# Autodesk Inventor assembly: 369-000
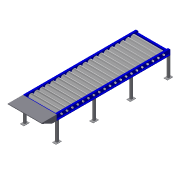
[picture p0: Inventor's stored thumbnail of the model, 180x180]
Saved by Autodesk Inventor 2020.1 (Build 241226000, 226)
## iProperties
Manager: www.cadconsulting.pl
Company: Fabian Stasiak CAD Consulting
Created: 2005-09
Part Number: 369-000
Document SubType Name: Assembly
Designer: F.Stasiak
Project: Przenośnik XC850
Description: Przenośnik rolkowy XC850
Authority: B.S.
Title: Przenośnik rolkowy
Subject: Zbiór ćwiczeń. Autodesk Inventor 2020. Kurs podstawowy
Author: F.Stasiak
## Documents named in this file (11)
- C:\2020_Kurs_podstawowy\R9 Zarządzanie plikami\369-000.iam
- C:\2020_Kurs_podstawowy\R9 Zarządzanie plikami\Bok_prawy.ipt
- C:\2020_Kurs_podstawowy\R9 Zarządzanie plikami\Poprzeczka.ipt
- C:\2020_Kurs_podstawowy\R9 Zarządzanie plikami\123-004.ipt
- C:\2020_Kurs_podstawowy\R9 Zarządzanie plikami\Rolka.ipt
- C:\2020_Kurs_podstawowy\R9 Zarządzanie plikami\Bok_lewy.ipt
- C:\2020_Kurs_podstawowy\R9 Zarządzanie plikami\475-001.ipt
- C:\2020_Kurs_podstawowy\R9 Zarządzanie plikami\369-000\Design Accelerator\Połączenie gwintowe5.iam
- C:\2020_Kurs_podstawowy\R9 Zarządzanie plikami\369-000\Design Accelerator\Połączenie gwintowe6.iam
- C:\2020_Kurs_podstawowy\R9 Zarządzanie plikami\369-000\Design Accelerator\Połączenie gwintowe7.iam
- C:\2020_Kurs_podstawowy\R9 Zarządzanie plikami\369-000\Design Accelerator\Połączenie gwintowe9.iam
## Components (37 placed, 7 different names)
1. Bok_prawy:1 — Zestawiający:2, Równoległy:8, Równoległy:9, Zestawiający:4, Wstaw:2, Równoległy:10, Równoległy:11, Zestawiający:5, Równoległy:12, Równoległy:13, Zestawiający:7, Równoległy:14, Równoległy:15
2. Bok_lewy:1 — Równoległy:10, Równoległy:11, Zestawiający:5, Wstaw:3, Zestawiający:6, Równoległy:16
3. Poprzeczka:1 — Zestawiający:2, Zestawiający:6
4. Poprzeczka:2 — Równoległy:12, Równoległy:13
5. 475-001:1 — Zestawiający:7, Równoległy:14, Równoległy:15, Równoległy:16, Zestawiający:8, Zestawiający:9, Zestawiający:10, Zestawiający:11, Zestawiający:12, Zestawiający:13, Zestawiający:14, Zestawiający:15
6. Połączenie gwintowe:1 [sub-assembly] — Zestawiający:8, Zestawiający:9
7. Połączenie gwintowe:2 [sub-assembly] — Zestawiający:10, Zestawiający:11
8. Połączenie gwintowe:3 [sub-assembly] — Zestawiający:12, Zestawiający:13
9. Połączenie gwintowe:4 [sub-assembly] — Zestawiający:14, Zestawiający:15
10. 123-004:1 — Równoległy:8, Równoległy:9, Zestawiający:4
11. 123-004:2
12. 123-004:3
13. 123-004:4
14. 123-004:5
15. 123-004:6
16. 123-004:7
17. 123-004:8
18. Rolka:1 — Wstaw:2, Wstaw:3
19. Rolka:2
20. Rolka:3
21. Rolka:4
22. Rolka:5
23. Rolka:6
24. Rolka:7
25. Rolka:8
26. Rolka:9
27. Rolka:10
28. Rolka:11
29. Rolka:12
30. Rolka:13
31. Rolka:14
32. Rolka:15
33. Rolka:16
34. Rolka:17
35. Rolka:18
36. Rolka:19
37. Rolka:20
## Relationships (24: Mate 13, Flush 9, Insert 2)
- Zestawiający:2 [Mate]: Bok_prawy:1 ↔ Poprzeczka:1
- Równoległy:8 [Flush]: Bok_prawy:1 ↔ 123-004:1
- Równoległy:9 [Flush]: Bok_prawy:1 ↔ 123-004:1
- Zestawiający:4 [Mate]: Bok_prawy:1 ↔ 123-004:1
- Wstaw:2 [Insert]: Bok_prawy:1 ↔ Rolka:1
- Równoległy:10 [Flush]: Bok_prawy:1 ↔ Bok_lewy:1
- Równoległy:11 [Flush]: Bok_prawy:1 ↔ Bok_lewy:1
- Zestawiający:5 [Mate]: Bok_prawy:1 ↔ Bok_lewy:1
- Wstaw:3 [Insert]: Bok_lewy:1 ↔ Rolka:1
- Zestawiający:6 [Mate]: Bok_lewy:1 ↔ Poprzeczka:1
- Równoległy:12 [Flush]: Bok_prawy:1 ↔ Poprzeczka:2
- Równoległy:13 [Flush]: Bok_prawy:1 ↔ Poprzeczka:2
- Zestawiający:7 [Mate]: Bok_prawy:1 ↔ 475-001:1
- Równoległy:14 [Flush]: Bok_prawy:1 ↔ 475-001:1
- Równoległy:15 [Flush]: Bok_prawy:1 ↔ 475-001:1
- Równoległy:16 [Flush]: Bok_lewy:1 ↔ 475-001:1
- Zestawiający:8 [Mate]: 475-001:1 ↔ Połączenie gwintowe:1
- Zestawiający:9 [Mate]: 475-001:1 ↔ Połączenie gwintowe:1
- Zestawiający:10 [Mate]: 475-001:1 ↔ Połączenie gwintowe:2
- Zestawiający:11 [Mate]: 475-001:1 ↔ Połączenie gwintowe:2
- Zestawiający:12 [Mate]: 475-001:1 ↔ Połączenie gwintowe:3
- Zestawiający:13 [Mate]: 475-001:1 ↔ Połączenie gwintowe:3
- Zestawiający:14 [Mate]: 475-001:1 ↔ Połączenie gwintowe:4
- Zestawiający:15 [Mate]: 475-001:1 ↔ Połączenie gwintowe:4
